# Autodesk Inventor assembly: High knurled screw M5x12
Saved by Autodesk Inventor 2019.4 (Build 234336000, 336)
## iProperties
Created: 2021-08
Part Number: High knurled screw M5x12
Document SubType Name: Assembly
Designer: Administrator
Title: High knurled screw M5x12 v5
Author: Administrator
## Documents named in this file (2)
- c:\worker\convert-fusion-r06\tmp\job-1\20\output\files\f01db8e3-9ba6-469c-91a4-18b8ab1b818d\High knurled screw M5x12 v5.iam
- c:\worker\convert-fusion-r06\tmp\job-1\20\output\files\f01db8e3-9ba6-469c-91a4-18b8ab1b818d\_Knurled screw DIN 464-M5-12-ZB.ipt
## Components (1 placed, 1 different names)
1. _Knurled screw DIN 464-M5-12-ZB:1
